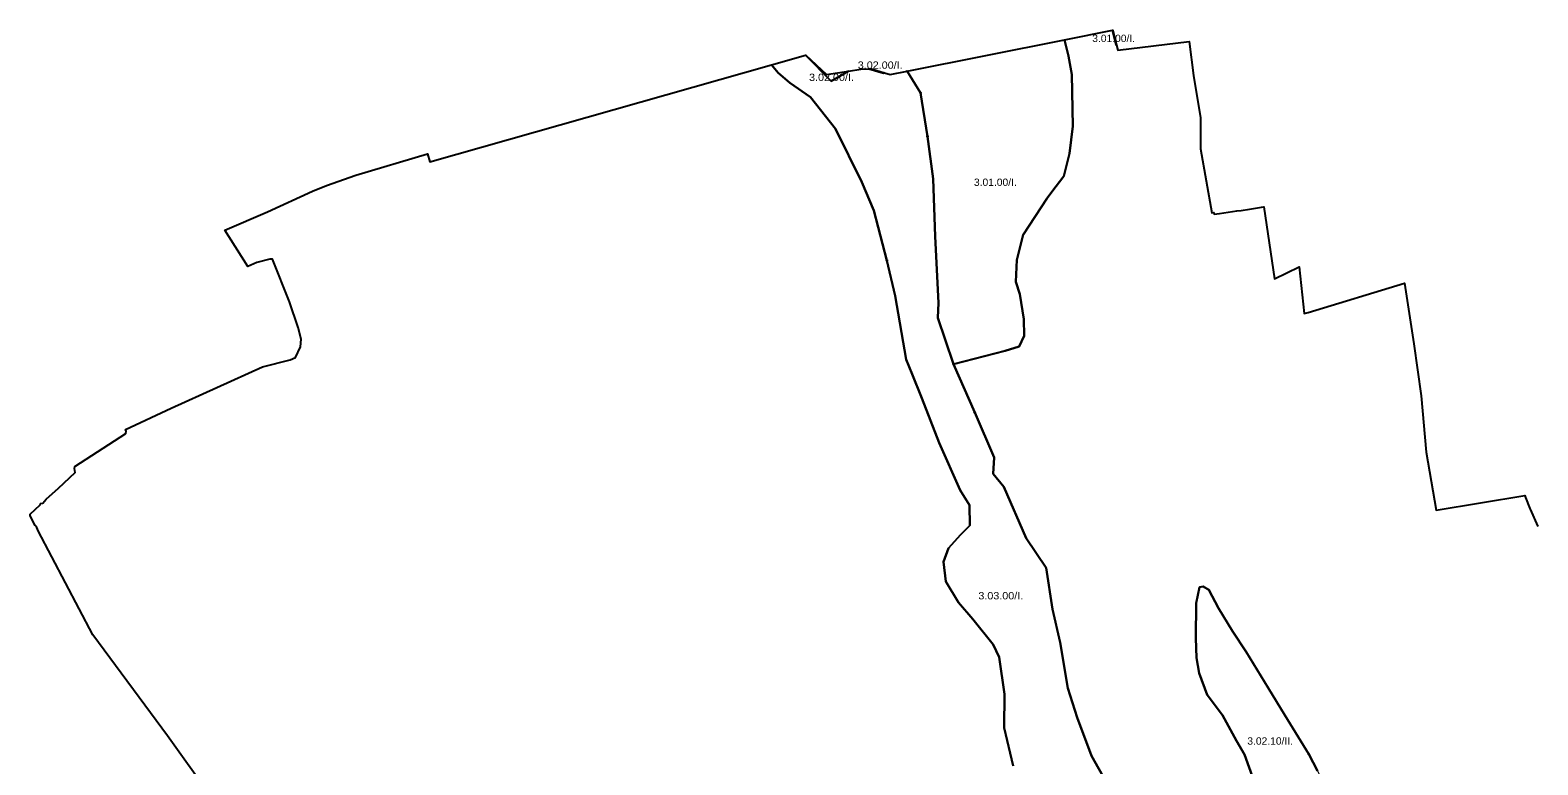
# Model space of a CAD drawing. Extents: x -650455 to -642254, y -1075222 to -1066610.
# Drawn here: x -649749 to -647688, y -1067615 to -1066610 of the extents above; entities that cross this region are included whole.
import ezdxf
from ezdxf.enums import TextEntityAlignment as Align

# ---------------------------------------------------------------- set-up
doc = ezdxf.new("R2010")
doc.units = 0
doc.header["$LTSCALE"] = 4
doc.header["$PDMODE"] = 32
doc.header["$PDSIZE"] = 2
for name, color, linetype, lineweight in [('1', 7, 'Continuous', 25), ('11', 7, 'Continuous', 13), ('12', 7, 'Continuous', 13)]:
    doc.layers.add(name, color=color, linetype=linetype, lineweight=lineweight)
doc.layers.add('2', color=7, linetype='Continuous')

msp = doc.modelspace()

# ---------------------------------------------------------------- linework, layer by layer
at = {"layer": '1'}
for points in [[(-648389.757, -1067028.33), (-648390.545, -1067005.888), (-648395.663, -1066971.636), (-648401.175, -1066954.707), (-648399.993, -1066924.392), (-648391.332, -1066890.534), (-648358.655, -1066840.338), (-648351.842, -1066831.446), (-648335.426, -1066810.022), (-648327.946, -1066779.314), (-648323.222, -1066741.912), (-648324.797, -1066671.242), (-648329.302, -1066646.114), (-648334.619, -1066623.566), (-648269.072, -1066610.457)], [(-648269.072, -1066610.457), (-648264.273, -1066631.023), (-648263.63, -1066630.927), (-648261.93, -1066637.9), (-648164.367, -1066625.78), (-648158.341, -1066672.5), (-648148.902, -1066730.306), (-648148.951, -1066772.833), (-648133.428, -1066860.414), (-648130.692, -1066859.934), (-648130.3, -1066862.191), (-648122.93, -1066861.231), (-648099.18, -1066857.711), (-648093.27, -1066856.88), (-648081.68, -1066855.07), (-648065.35, -1066852.43), (-648062.151, -1066851.997), (-648047.62, -1066950.472), (-648013.972, -1066934.121), (-648006.88, -1066997.861), (-648001.56, -1066996.48), (-647870.096, -1066956.326), (-647870.071, -1066956.488), (-647857.238, -1067039.257), (-647847.07, -1067110.742), (-647840.09, -1067187.6), (-647826.6, -1067266.851), (-647705.237, -1067247.08), (-647704.494, -1067249.583), (-647698.66, -1067264.805), (-647698.194, -1067265.832), (-647687.428, -1067289.554)], [(-649739.715, -1067290.835), (-649741.973, -1067288.013), (-649748.747, -1067274.889), (-649748.888, -1067272.348), (-649735.058, -1067259.788), (-649734.776, -1067258.093), (-649731.389, -1067257.388), (-649726.872, -1067251.742), (-649709.937, -1067237.066), (-649687.498, -1067215.474), (-649688.345, -1067209.829), (-649687.921, -1067207.146), (-649618.205, -1067162.127), (-649617.499, -1067159.022), (-649618.487, -1067156.624), (-649555.967, -1067127.268), (-649431.221, -1067070.904), (-649393.591, -1067061.314), (-649386.276, -1067058.37), (-649379.197, -1067043.511), (-649378.49, -1067033.048), (-649382.484, -1067017.277), (-649394.246, -1066982.08), (-649417.645, -1066923.797), (-649421.315, -1066923.466), (-649438.75, -1066928.315), (-649451.255, -1066933.461), (-649482.498, -1066883.996), (-649424.448, -1066858.847), (-649362.767, -1066830.547), (-649343.909, -1066823.005), (-649303.521, -1066808.913), (-649205.811, -1066779.789), (-649205.758, -1066779.773), (-649202.23, -1066790.46), (-648735.154, -1066657.714), (-648726.371, -1066668.881), (-648710.229, -1066682.66), (-648681.883, -1066701.951), (-648648.025, -1066745.259)], [(-648464.166, -1067288.173), (-648464.56, -1067260.22), (-648477.552, -1067239.551), (-648505.899, -1067174.983), (-648529.914, -1067113.959), (-648543.12, -1067081.069), (-648551.174, -1067061.007), (-648566.135, -1066973.606), (-648577.552, -1066925.376), (-648595.269, -1066857.266), (-648611.804, -1066818.29), (-648648.025, -1066745.259), (-648681.883, -1066701.951), (-648710.229, -1066682.66), (-648726.371, -1066668.881), (-648735.154, -1066657.714), (-648689.065, -1066644.615), (-648653.93, -1066680.101), (-648630.032, -1066666.4)], [(-648630.032, -1066666.4), (-648612.98, -1066663.84), (-648602.348, -1066663.52), (-648582.277, -1066669.077), (-648580.928, -1066668.794), (-648573, -1066671.24), (-648549.953, -1066666.631), (-648531.489, -1066696.244), (-648522.04, -1066755.692), (-648514.166, -1066813.762), (-648511.411, -1066892.502), (-648507.08, -1066983.25), (-648507.867, -1067003.92), (-648487.001, -1067066.125), (-648486.395, -1067067.508), (-648457.474, -1067133.448), (-648431.096, -1067195.061), (-648432.277, -1067217.109), (-648417.71, -1067235.22), (-648387.001, -1067305.496), (-648359.836, -1067346.047), (-648351.174, -1067402.543), (-648340.544, -1067448.211), (-648330.308, -1067510.614), (-648317.316, -1067550.573), (-648298.025, -1067602.935), (-648272.04, -1067649.196)], [(-648648.025, -1066745.259), (-648611.804, -1066818.29), (-648595.269, -1066857.266), (-648577.552, -1066925.376), (-648566.135, -1066973.606), (-648551.174, -1067061.007), (-648543.12, -1067081.069), (-648529.914, -1067113.959), (-648505.899, -1067174.983), (-648477.552, -1067239.551), (-648464.56, -1067260.22), (-648464.166, -1067288.173), (-648476.765, -1067300.771), (-648493.3, -1067318.88), (-648500.387, -1067337.778), (-648496.844, -1067364.551), (-648479.521, -1067393.29), (-648460.229, -1067416.321), (-648432.277, -1067450.573), (-648424.009, -1067468.29), (-648416.922, -1067518.685), (-648417.316, -1067564.943), (-648405.111, -1067616.518)], [(-648272.04, -1067649.196), (-648298.025, -1067602.935), (-648317.316, -1067550.573), (-648330.308, -1067510.614), (-648340.544, -1067448.211), (-648351.174, -1067402.543), (-648359.836, -1067346.047), (-648387.001, -1067305.496), (-648417.71, -1067235.22), (-648432.277, -1067217.109), (-648431.096, -1067195.061), (-648457.474, -1067133.448), (-648486.395, -1067067.508), (-648416, -1067049), (-648396.665, -1067042.959), (-648389.757, -1067028.33)], [(-649502.696, -1067657.083), (-649561.33, -1067575.772), (-649663.224, -1067437.749), (-649738.022, -1067295.211), (-649739.715, -1067290.835)], [(-648405.111, -1067616.518), (-648417.316, -1067564.943), (-648416.922, -1067518.685), (-648424.009, -1067468.29), (-648432.277, -1067450.573), (-648460.229, -1067416.321), (-648479.521, -1067393.29), (-648496.844, -1067364.551), (-648500.387, -1067337.778), (-648493.3, -1067318.88), (-648476.765, -1067300.771), (-648464.166, -1067288.173)], [(-648075.978, -1067636.99), (-648088.576, -1067601.164), (-648099.6, -1067582.66), (-648118.891, -1067547.62), (-648139.757, -1067519.472), (-648150.781, -1067489.944), (-648154.324, -1067469.078), (-648155.111, -1067442.306), (-648154.718, -1067394.274), (-648150.387, -1067372.424), (-648145.269, -1067371.243), (-648137.395, -1067375.968), (-648124.009, -1067401.165), (-648105.111, -1067432.66), (-648086.214, -1067461.007), (-648056.293, -1067510.22), (-648033.458, -1067547.424), (-648000.781, -1067600.573), (-647988.97, -1067623.408)], [(-647988.97, -1067623.408), (-648000.781, -1067600.573), (-648033.458, -1067547.424), (-648056.293, -1067510.22), (-648086.214, -1067461.007), (-648105.111, -1067432.66), (-648124.009, -1067401.165), (-648137.395, -1067375.968), (-648145.269, -1067371.243), (-648150.387, -1067372.424), (-648154.718, -1067394.274), (-648155.111, -1067442.306), (-648154.324, -1067469.078), (-648150.781, -1067489.944), (-648139.757, -1067519.472), (-648118.891, -1067547.62), (-648099.6, -1067582.66), (-648088.576, -1067601.164), (-648075.978, -1067636.99)]]:
    msp.add_lwpolyline(points, dxfattribs=at)
for points in [[(-648263.63, -1066630.927), (-648264.273, -1066631.023), (-648269.072, -1066610.457), (-648268.64, -1066610.371)], [(-648486.395, -1067067.508), (-648487.001, -1067066.125), (-648507.867, -1067003.92), (-648507.08, -1066983.25), (-648511.411, -1066892.502), (-648514.166, -1066813.762), (-648522.04, -1066755.692), (-648531.489, -1066696.244), (-648549.953, -1066666.631), (-648334.619, -1066623.566), (-648329.302, -1066646.114), (-648324.797, -1066671.242), (-648323.222, -1066741.912), (-648327.946, -1066779.314), (-648335.426, -1066810.022), (-648351.842, -1066831.446), (-648358.655, -1066840.338), (-648391.332, -1066890.534), (-648399.993, -1066924.392), (-648401.175, -1066954.707), (-648395.663, -1066971.636), (-648390.545, -1067005.888), (-648389.757, -1067028.33), (-648396.665, -1067042.959), (-648416, -1067049)], [(-648630.032, -1066666.4), (-648653.93, -1066680.101), (-648689.065, -1066644.615), (-648688.24, -1066644.381), (-648659.95, -1066670.891)], [(-648580.928, -1066668.794), (-648582.277, -1066669.077), (-648602.348, -1066663.52), (-648598.4, -1066663.401)]]:
    msp.add_lwpolyline(points, close=True, dxfattribs=at)
at = {"layer": '11'}
for p, q in [((-648549.953, -1066666.631), (-648531.489, -1066696.244)), ((-648531.489, -1066696.244), (-648522.04, -1066755.692)), ((-648487.001, -1067066.125), (-648486.395, -1067067.508))]:
    msp.add_line(p, q, dxfattribs=at)
for points in [[(-647687.428, -1067289.554), (-647698.194, -1067265.832), (-647698.66, -1067264.805), (-647704.494, -1067249.583), (-647705.237, -1067247.08), (-647826.6, -1067266.851), (-647840.09, -1067187.6), (-647847.07, -1067110.742), (-647857.238, -1067039.257), (-647870.071, -1066956.488), (-647870.096, -1066956.326), (-648001.56, -1066996.48), (-648006.88, -1066997.861), (-648013.972, -1066934.121), (-648047.62, -1066950.472), (-648062.151, -1066851.997), (-648065.35, -1066852.43), (-648081.68, -1066855.07), (-648093.27, -1066856.88), (-648099.18, -1066857.711), (-648122.93, -1066861.231), (-648130.3, -1066862.191), (-648130.692, -1066859.934), (-648133.428, -1066860.414), (-648148.951, -1066772.833), (-648148.902, -1066730.306), (-648158.341, -1066672.5), (-648164.367, -1066625.78), (-648261.93, -1066637.9), (-648263.63, -1066630.927), (-648264.273, -1066631.023), (-648269.072, -1066610.457), (-648334.619, -1066623.566), (-648329.302, -1066646.114)], [(-648486.395, -1067067.508), (-648416, -1067049), (-648396.665, -1067042.959), (-648389.757, -1067028.33), (-648390.545, -1067005.888), (-648395.663, -1066971.636), (-648401.175, -1066954.707), (-648399.993, -1066924.392), (-648391.332, -1066890.534), (-648358.655, -1066840.338), (-648351.842, -1066831.446), (-648335.426, -1066810.022), (-648327.946, -1066779.314), (-648323.222, -1066741.912), (-648324.797, -1066671.242), (-648329.302, -1066646.114), (-648334.619, -1066623.566), (-648549.953, -1066666.631)], [(-648405.111, -1067616.518), (-648417.316, -1067564.943), (-648416.922, -1067518.685), (-648424.009, -1067468.29), (-648432.277, -1067450.573), (-648460.229, -1067416.321), (-648479.521, -1067393.29), (-648496.844, -1067364.551), (-648500.387, -1067337.778), (-648493.3, -1067318.88), (-648476.765, -1067300.771), (-648464.166, -1067288.173), (-648464.56, -1067260.22), (-648477.552, -1067239.551), (-648505.899, -1067174.983), (-648529.914, -1067113.959), (-648543.12, -1067081.069), (-648551.174, -1067061.007), (-648566.135, -1066973.606), (-648577.552, -1066925.376), (-648595.269, -1066857.266), (-648611.804, -1066818.29), (-648648.025, -1066745.259), (-648681.883, -1066701.951), (-648710.229, -1066682.66), (-648726.371, -1066668.881), (-648735.154, -1066657.714), (-649202.23, -1066790.46), (-649205.758, -1066779.773), (-649205.811, -1066779.789), (-649303.521, -1066808.913), (-649343.909, -1066823.005), (-649362.767, -1066830.547), (-649424.448, -1066858.847), (-649482.498, -1066883.996), (-649451.255, -1066933.461)], [(-648457.474, -1067133.448), (-648486.395, -1067067.508), (-648487.001, -1067066.125), (-648507.867, -1067003.92), (-648507.08, -1066983.25), (-648511.411, -1066892.502), (-648514.166, -1066813.762), (-648522.04, -1066755.692), (-648531.489, -1066696.244), (-648549.953, -1066666.631), (-648573, -1066671.24), (-648580.928, -1066668.794), (-648582.277, -1066669.077), (-648602.348, -1066663.52), (-648612.98, -1066663.84), (-648630.032, -1066666.4), (-648653.93, -1066680.101), (-648689.065, -1066644.615), (-648735.154, -1066657.714), (-648726.371, -1066668.881), (-648710.229, -1066682.66), (-648681.883, -1066701.951), (-648648.025, -1066745.259), (-648611.804, -1066818.29), (-648595.269, -1066857.266), (-648577.552, -1066925.376)], [(-648329.302, -1066646.114), (-648324.797, -1066671.242), (-648323.222, -1066741.912), (-648327.946, -1066779.314), (-648335.426, -1066810.022), (-648351.842, -1066831.446), (-648358.655, -1066840.338), (-648391.332, -1066890.534), (-648399.993, -1066924.392), (-648401.175, -1066954.707), (-648395.663, -1066971.636), (-648390.545, -1067005.888), (-648389.757, -1067028.33), (-648396.665, -1067042.959), (-648416, -1067049), (-648486.395, -1067067.508), (-648457.474, -1067133.448), (-648431.096, -1067195.061), (-648432.277, -1067217.109), (-648417.71, -1067235.22), (-648387.001, -1067305.496), (-648359.836, -1067346.047), (-648351.174, -1067402.543), (-648340.544, -1067448.211), (-648330.308, -1067510.614), (-648317.316, -1067550.573), (-648298.025, -1067602.935), (-648272.04, -1067649.196)], [(-648522.04, -1066755.692), (-648514.166, -1066813.762), (-648511.411, -1066892.502), (-648507.08, -1066983.25), (-648507.867, -1067003.92), (-648487.001, -1067066.125)], [(-649451.255, -1066933.461), (-649438.75, -1066928.315), (-649421.315, -1066923.466), (-649417.645, -1066923.797), (-649394.246, -1066982.08), (-649382.484, -1067017.277), (-649378.49, -1067033.048), (-649379.197, -1067043.511), (-649386.276, -1067058.37), (-649393.591, -1067061.314), (-649431.221, -1067070.904), (-649555.967, -1067127.268), (-649618.487, -1067156.624), (-649617.499, -1067159.022), (-649618.205, -1067162.127), (-649687.921, -1067207.146), (-649688.345, -1067209.829), (-649687.498, -1067215.474), (-649709.937, -1067237.066), (-649726.872, -1067251.742), (-649731.389, -1067257.388), (-649734.776, -1067258.093), (-649735.058, -1067259.788), (-649748.888, -1067272.348), (-649748.747, -1067274.889), (-649741.973, -1067288.013), (-649739.715, -1067290.835), (-649738.022, -1067295.211), (-649663.224, -1067437.749), (-649561.33, -1067575.772), (-649502.696, -1067657.083)], [(-648577.552, -1066925.376), (-648566.135, -1066973.606), (-648551.174, -1067061.007), (-648543.12, -1067081.069), (-648529.914, -1067113.959), (-648505.899, -1067174.983), (-648477.552, -1067239.551), (-648464.56, -1067260.22), (-648464.166, -1067288.173), (-648476.765, -1067300.771), (-648493.3, -1067318.88), (-648500.387, -1067337.778), (-648496.844, -1067364.551), (-648479.521, -1067393.29), (-648460.229, -1067416.321), (-648432.277, -1067450.573), (-648424.009, -1067468.29), (-648416.922, -1067518.685), (-648417.316, -1067564.943), (-648405.111, -1067616.518)], [(-648242.907, -1067685.417), (-648272.04, -1067649.196), (-648298.025, -1067602.935), (-648317.316, -1067550.573), (-648330.308, -1067510.614), (-648340.544, -1067448.211), (-648351.174, -1067402.543), (-648359.836, -1067346.047), (-648387.001, -1067305.496), (-648417.71, -1067235.22), (-648432.277, -1067217.109), (-648431.096, -1067195.061), (-648457.474, -1067133.448)], [(-648154.324, -1067469.078), (-648155.111, -1067442.306), (-648154.718, -1067394.274), (-648150.387, -1067372.424), (-648145.269, -1067371.243), (-648137.395, -1067375.968), (-648124.009, -1067401.165), (-648105.111, -1067432.66), (-648086.214, -1067461.007), (-648056.293, -1067510.22), (-648033.458, -1067547.424), (-648000.781, -1067600.573)], [(-648075.978, -1067636.99), (-648088.576, -1067601.164), (-648099.6, -1067582.66), (-648118.891, -1067547.62), (-648139.757, -1067519.472), (-648150.781, -1067489.944), (-648154.324, -1067469.078)], [(-648000.781, -1067600.573), (-647988.97, -1067623.408), (-647981.489, -1067638.368), (-647979.521, -1067686.99), (-647979.521, -1067735.023), (-647978.34, -1067766.913), (-647970.859, -1067807.66), (-647953.93, -1067873.014), (-647940.151, -1067933.053), (-647916.922, -1067998.802)]]:
    msp.add_lwpolyline(points, dxfattribs=at)
for points in [[(-648264.273, -1066631.023), (-648263.63, -1066630.927), (-648268.64, -1066610.371), (-648269.072, -1066610.457)], [(-648653.93, -1066680.101), (-648630.032, -1066666.4), (-648659.95, -1066670.891), (-648688.24, -1066644.381), (-648689.065, -1066644.615)], [(-648582.277, -1066669.077), (-648580.928, -1066668.794), (-648598.4, -1066663.401), (-648602.348, -1066663.52)]]:
    msp.add_lwpolyline(points, close=True, dxfattribs=at)
for p in [(-648549.953, -1066666.631), (-648531.489, -1066696.244), (-648522.04, -1066755.692), (-648577.552, -1066925.376), (-648486.395, -1067067.508), (-648457.474, -1067133.448), (-648000.781, -1067600.573)]:
    msp.add_point(p, dxfattribs=at)
at = {"layer": '12'}
msp.add_lwpolyline([(-647988.97, -1067623.408), (-648000.781, -1067600.573), (-648033.458, -1067547.424), (-648056.293, -1067510.22), (-648086.214, -1067461.007), (-648105.111, -1067432.66), (-648124.009, -1067401.165), (-648137.395, -1067375.968), (-648145.269, -1067371.243), (-648150.387, -1067372.424), (-648154.718, -1067394.274), (-648155.111, -1067442.306), (-648154.324, -1067469.078), (-648150.781, -1067489.944), (-648139.757, -1067519.472), (-648118.891, -1067547.62), (-648099.6, -1067582.66), (-648088.576, -1067601.164), (-648075.978, -1067636.99)], dxfattribs=at)

# ---------------------------------------------------------------- texts
at = {"layer": '2'}
for s, width, p in [('3.01.00/I.', 1.05, (-648267.52, -1066626.61)), ('3.02.00/I.', 1.1, (-648586.704, -1066663.184)), ('3.02.00/I.', 1.1, (-648653.301, -1066679.895)), ('3.01.00/I.', 1.05, (-648429.264, -1066823.422)), ('3.03.00/I.', 1.1, (-648421.85, -1067389.046)), ('3.02.10/II.', 1.05, (-648053.576, -1067587.758))]:
    msp.add_text(s, height=10, dxfattribs=dict(at, width=width)).set_placement(p, align=Align.CENTER)

doc.saveas('drawing.dxf')
